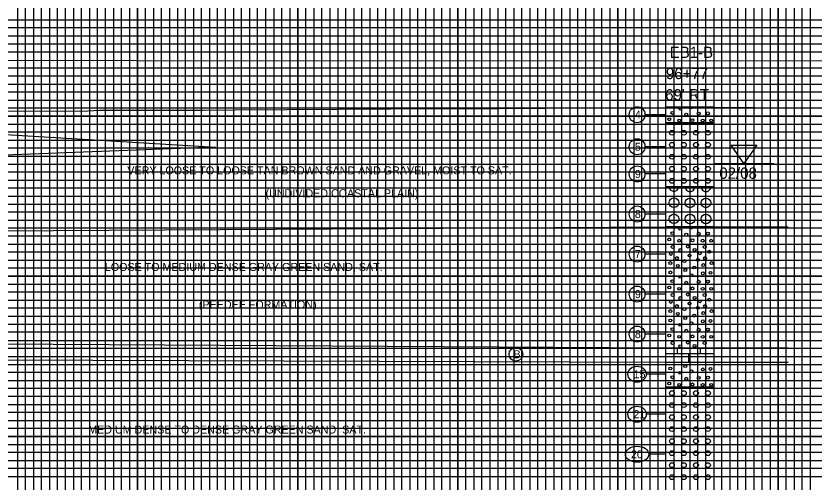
# Model space of a CAD drawing. Extents: x -13 to 886, y -5 to 434.
# Drawn here: x 707.1 to 806.7, y 265.2 to 323.4 of the extents above; entities that cross this region are included whole.
import ezdxf

# ---------------------------------------------------------------- set-up
doc = ezdxf.new("R2010")
doc.units = 0
for name, color, linetype in [('Exist XS Ground Line', 7, 'Continuous'), ('Prop Road Sect_ Boring - Header Labels from Geopak', 7, 'Continuous'), ('Prop Road Sect_ Boring - Material (Outline)', 7, 'Continuous'), ('Prop Road Sect_ Boring - Peripheral (24 Hr GrdWtr Date)', 7, 'Continuous'), ('Prop Road Sect_ Boring - Peripheral (SPT Oval + Leader)', 7, 'Continuous'), ('Prop Road Sect_ Boring - Peripheral (SPT Tx)', 7, 'Continuous'), ('Prop Road Sect_ Material - Contact (General - Minor)', 7, 'Continuous'), ('Prop Road Sect_ Material - Tx (Composite Desc)', 7, 'Continuous'), ('Sheet Cross Section Grid Major CELL', 7, 'Continuous'), ('Sheet Cross Section Grid Middle CELL', 7, 'Continuous'), ('Sheet Cross Section Grid Minor 1 CELL', 7, 'Continuous'), ('Sheet Cross Section Grid Minor 2 CELL', 7, 'Continuous'), ('Sheet DOT Grid CELL', 7, 'Continuous'), ('Water Mark (24 Hr) Cell', 7, 'Continuous')]:
    doc.layers.add(name, color=color, linetype=linetype)

msp = doc.modelspace()

# ---------------------------------------------------------------- linework, layer by layer
at = {"layer": 'Exist XS Ground Line'}
for points in [[(650.115, 311.763), (652.113, 311.781), (666.089, 311.684), (668.65, 311.535), (672.715, 311.547), (682.507, 311.512), (686.055, 311.503), (690.603, 311.476), (715.981, 311.545), (717.469, 311.623), (722.243, 311.635), (730.438, 311.655), (734.382, 311.675), (760.339, 311.838), (767.402, 311.852), (778.837, 311.921), (784.232, 311.947)], [(785.181, 311.951), (799.343, 312.019)]]:
    msp.add_lwpolyline(points, dxfattribs=at)
at = {"layer": 'Prop Road Sect_ Boring - Material (Outline)'}
for p, q in [((788.25, 281.97), (794.237, 281.97)), ((788.25, 280.171), (794.237, 280.171))]:
    msp.add_line(p, q, dxfattribs=at)
for points in [[(788.243, 312.077), (794.243, 312.077), (794.243, 310.077), (788.243, 310.077)], [(788.243, 310.077), (794.243, 310.077), (794.243, 302.077), (788.243, 302.077)], [(788.243, 302.077), (794.243, 302.077), (794.243, 297.077), (788.243, 297.077)], [(788.243, 297.077), (794.243, 297.077), (794.243, 277.077), (788.243, 277.077)], [(788.243, 277.077), (794.243, 277.077), (794.243, 262.077), (788.243, 262.077)]]:
    msp.add_lwpolyline(points, close=True, dxfattribs=at)
for centre, radius in [((789.045, 311.296), 0.18), ((790.026, 311.842), 0.18), ((790.788, 311.107), 0.18), ((792.339, 311.227), 0.18), ((793.485, 311.245), 0.18), ((788.664, 310.51), 0.18), ((789.888, 310.345), 0.18), ((791.55, 310.399), 0.18), ((792.831, 310.345), 0.18), ((793.893, 310.345), 0.18), ((788.99, 308.819), 0.3), ((790.49, 308.819), 0.3), ((791.99, 308.819), 0.3), ((793.49, 308.819), 0.3), ((788.99, 307.322), 0.3), ((790.49, 307.322), 0.3), ((791.99, 307.322), 0.3), ((793.49, 307.322), 0.3), ((788.99, 305.822), 0.3), ((790.49, 305.822), 0.3), ((791.99, 305.822), 0.3), ((793.49, 305.822), 0.3), ((788.99, 304.322), 0.3), ((790.49, 304.322), 0.3), ((791.99, 304.322), 0.3), ((793.49, 304.322), 0.3), ((788.99, 302.822), 0.3), ((790.49, 302.822), 0.3), ((791.99, 302.822), 0.3), ((793.49, 302.822), 0.3), ((789.241, 300.089), 0.6), ((791.251, 300.065), 0.6), ((793.237, 300.065), 0.6), ((789.241, 298.079), 0.6), ((791.251, 298.055), 0.6), ((793.237, 298.055), 0.6), ((789.045, 296.287), 0.18), ((790.026, 296.833), 0.18), ((790.788, 296.098), 0.18), ((792.339, 296.218), 0.18), ((793.485, 296.236), 0.18), ((788.664, 295.501), 0.18), ((789.888, 295.336), 0.18), ((791.55, 295.39), 0.18), ((792.831, 295.336), 0.18), ((793.893, 295.336), 0.18), ((789.082, 294.563), 0.18), ((790.038, 294.173), 0.18), ((790.973, 294.609), 0.18), ((791.82, 294.194), 0.18), ((793.082, 294.563), 0.18), ((793.674, 293.968), 0.18), ((788.856, 293.695), 0.18), ((789.618, 293.179), 0.18), ((791.183, 293.498), 0.18), ((792.231, 292.96), 0.18), ((792.477, 293.776), 0.18), ((793.131, 293.179), 0.18), ((788.802, 292.552), 0.18), ((789.726, 292.198), 0.18), ((790.542, 292.798), 0.18), ((791.784, 291.991), 0.18), ((792.912, 292.306), 0.18), ((793.947, 292.552), 0.18), ((788.802, 291.382), 0.18), ((790.656, 291.682), 0.18), ((791.43, 291.034), 0.18), ((792.858, 291.271), 0.18), ((793.812, 291.328), 0.18), ((789.045, 290.29), 0.18), ((790.026, 290.836), 0.18), ((790.788, 290.101), 0.18), ((792.339, 290.221), 0.18), ((793.485, 290.239), 0.18), ((788.664, 289.504), 0.18), ((789.888, 289.339), 0.18), ((791.55, 289.393), 0.18), ((792.831, 289.339), 0.18), ((793.893, 289.339), 0.18), ((789.082, 288.566), 0.18), ((790.038, 288.176), 0.18), ((790.973, 288.612), 0.18), ((791.82, 288.197), 0.18), ((793.082, 288.566), 0.18), ((793.674, 287.971), 0.18), ((788.856, 287.698), 0.18), ((789.618, 287.182), 0.18), ((791.183, 287.501), 0.18), ((792.231, 286.963), 0.18), ((792.477, 287.779), 0.18), ((793.131, 287.182), 0.18), ((788.802, 286.555), 0.18), ((789.726, 286.201), 0.18), ((790.542, 286.801), 0.18), ((791.784, 285.994), 0.18), ((792.912, 286.309), 0.18), ((793.947, 286.555), 0.18), ((788.802, 285.385), 0.18), ((790.656, 285.685), 0.18), ((791.43, 285.037), 0.18), ((792.858, 285.274), 0.18), ((793.812, 285.331), 0.18), ((789.045, 284.293), 0.18), ((790.026, 284.839), 0.18), ((790.788, 284.104), 0.18), ((792.339, 284.224), 0.18), ((793.485, 284.242), 0.18), ((788.664, 283.507), 0.18), ((789.888, 283.342), 0.18), ((791.55, 283.396), 0.18), ((792.831, 283.342), 0.18), ((793.893, 283.342), 0.18), ((789.082, 282.569), 0.18), ((790.038, 282.179), 0.18), ((790.973, 282.615), 0.18), ((791.82, 282.2), 0.18), ((793.082, 282.569), 0.18), ((788.802, 279.388), 0.18), ((790.656, 279.688), 0.18), ((791.43, 279.04), 0.18), ((792.858, 279.277), 0.18), ((793.812, 279.334), 0.18), ((789.045, 278.296), 0.18), ((790.026, 278.842), 0.18), ((790.788, 278.107), 0.18), ((792.339, 278.227), 0.18), ((793.485, 278.245), 0.18), ((788.664, 277.51), 0.18), ((789.888, 277.345), 0.18), ((791.55, 277.399), 0.18), ((792.831, 277.345), 0.18), ((793.893, 277.345), 0.18), ((788.99, 276.316), 0.3), ((790.49, 276.316), 0.3), ((791.99, 276.316), 0.3), ((793.49, 276.316), 0.3), ((788.99, 274.816), 0.3), ((790.49, 274.816), 0.3), ((791.99, 274.816), 0.3), ((793.49, 274.816), 0.3), ((788.99, 273.319), 0.3), ((790.49, 273.319), 0.3), ((791.99, 273.319), 0.3), ((793.49, 273.319), 0.3), ((788.99, 271.819), 0.3), ((790.49, 271.819), 0.3), ((791.99, 271.819), 0.3), ((793.49, 271.819), 0.3), ((788.99, 270.319), 0.3), ((790.49, 270.319), 0.3), ((791.99, 270.319), 0.3), ((793.49, 270.319), 0.3), ((788.99, 268.819), 0.3), ((790.49, 268.819), 0.3), ((791.99, 268.819), 0.3), ((793.49, 268.819), 0.3), ((788.99, 267.322), 0.3), ((790.49, 267.322), 0.3), ((791.99, 267.322), 0.3), ((793.49, 267.322), 0.3), ((788.99, 265.822), 0.3), ((790.49, 265.822), 0.3), ((791.99, 265.822), 0.3), ((793.49, 265.822), 0.3)]:
    msp.add_circle(centre, radius, dxfattribs=at)
for centre, radius, start, end in [((791.43, 312.04), 0.18, 168.2251, 11.7749), ((788.99, 310.319), 0.3, 233.87938, 306.12062), ((790.49, 310.319), 0.3, 233.87938, 306.12062), ((791.99, 310.319), 0.3, 233.87938, 306.12062), ((793.49, 310.319), 0.3, 233.87938, 306.12062), ((789.241, 302.105), 0.6, 182.75672, 357.24328), ((791.251, 302.075), 0.6, 179.89087, 0.10913), ((793.237, 302.075), 0.6, 179.89087, 0.10913), ((791.43, 297.031), 0.18, 165.28168, 14.71832)]:
    msp.add_arc(centre, radius, start, end, dxfattribs=at)
at = {"layer": 'Prop Road Sect_ Boring - Peripheral (SPT Oval + Leader)'}
for p, q in [((788.243, 311.077), (785.626, 311.077)), ((788.243, 307.077), (785.626, 307.077)), ((788.243, 303.677), (785.626, 303.677)), ((788.243, 298.677), (785.626, 298.677)), ((788.243, 293.677), (785.626, 293.677)), ((788.243, 288.677), (785.626, 288.677)), ((788.243, 283.677), (785.626, 283.677)), ((788.25, 281.249), (793.995, 281.249)), ((789.682, 281.249), (789.682, 281.967)), ((791.12, 280.171), (791.12, 281.249)), ((792.557, 281.249), (792.557, 281.967)), ((793.998, 281.249), (794.237, 281.249)), ((788.243, 278.677), (785.792, 278.677)), ((788.243, 273.677), (785.792, 273.677)), ((788.243, 268.677), (786.115, 268.677))]:
    msp.add_line(p, q, dxfattribs=at)
for centre, major_axis, ratio in [((784.643, 311.077), (0, 1), 0.983465), ((784.643, 307.077), (0, 1), 0.983465), ((784.643, 303.677), (0, 1), 0.983465), ((784.643, 298.677), (0, 1), 0.983465), ((784.643, 293.677), (0, 1), 0.983465), ((784.643, 288.677), (0, 1), 0.983465), ((784.643, 283.677), (0, 1), 0.983465), ((784.643, 278.677), (1.149, 0), 0.870459), ((784.643, 273.677), (1.149, 0), 0.870459), ((784.643, 268.677), (1.472, 0), 0.679508)]:
    msp.add_ellipse(centre, major_axis=major_axis, ratio=ratio, dxfattribs=at)
at = {"layer": 'Prop Road Sect_ Material - Contact (General - Minor)'}
for p, q in [((691.243, 296.49), (788.243, 297.077)), ((794.243, 297.077), (803.525, 297.077)), ((691.301, 282.545), (788.25, 281.97)), ((794.237, 281.97), (803.519, 281.97)), ((691.301, 280.521), (788.25, 280.171)), ((794.237, 280.171), (803.519, 280.171))]:
    msp.add_line(p, q, dxfattribs=at)
msp.add_lwpolyline([(691.243, 309.49), (731.963, 307.005), (691.243, 305.49)], dxfattribs=at)
at = {"layer": 'Prop Road Sect_ Material - Tx (Composite Desc)'}
msp.add_circle((769.509, 281.166), 0.86, dxfattribs=at)
at = {"layer": 'Sheet Cross Section Grid Major CELL'}
for p, q in [((712.243, 200.903), (712.243, 410.903)), ((722.243, 410.903), (722.243, 200.903)), ((732.243, 200.903), (732.243, 410.903)), ((742.243, 410.903), (742.243, 200.903)), ((752.243, 200.903), (752.243, 410.903)), ((762.243, 410.903), (762.243, 200.903)), ((772.243, 200.903), (772.243, 410.903)), ((782.243, 410.903), (782.243, 200.903)), ((792.243, 200.903), (792.243, 410.903)), ((802.243, 410.903), (802.243, 200.903))]:
    msp.add_line(p, q, dxfattribs=at)
for points in [[(562.243, 320.903), (882.243, 320.903), (882.243, 310.903), (562.243, 310.903)], [(562.243, 300.903), (882.243, 300.903), (882.243, 290.903), (562.243, 290.903)], [(562.243, 280.903), (882.243, 280.903), (882.243, 270.903), (562.243, 270.903)]]:
    msp.add_lwpolyline(points, dxfattribs=at)
at = {"layer": 'Sheet Cross Section Grid Middle CELL'}
for points in [[(707.243, 410.903), (707.243, 200.903), (717.243, 200.903), (717.243, 410.903)], [(727.243, 410.903), (727.243, 200.903), (737.243, 200.903), (737.243, 410.903)], [(747.243, 410.903), (747.243, 200.903), (757.243, 200.903), (757.243, 410.903)], [(767.243, 410.903), (767.243, 200.903), (777.243, 200.903), (777.243, 410.903)], [(787.243, 410.903), (787.243, 200.903), (797.243, 200.903), (797.243, 410.903)], [(562.243, 305.903), (882.243, 305.903), (882.243, 315.903), (562.243, 315.903)], [(562.243, 285.903), (882.243, 285.903), (882.243, 295.903), (562.243, 295.903)], [(562.243, 265.903), (882.243, 265.903), (882.243, 275.903), (562.243, 275.903)]]:
    msp.add_lwpolyline(points, dxfattribs=at)
at = {"layer": 'Sheet Cross Section Grid Minor 1 CELL'}
for points in [[(562.243, 322.903), (882.243, 322.903), (882.243, 321.903), (562.243, 321.903)], [(562.243, 319.903), (882.243, 319.903), (882.243, 318.903), (562.243, 318.903)], [(562.243, 317.893), (882.313, 317.813), (882.243, 316.903), (562.243, 316.903)], [(562.243, 314.903), (882.243, 314.903), (882.243, 313.903), (562.243, 313.903)], [(562.243, 312.903), (882.243, 312.903), (882.243, 311.903), (562.243, 311.903)], [(562.243, 309.903), (882.243, 309.903), (882.243, 308.903), (562.243, 308.903)], [(562.243, 307.903), (882.243, 307.903), (882.243, 306.903), (562.243, 306.903)], [(562.243, 304.903), (882.243, 304.903), (882.243, 303.903), (562.243, 303.903)], [(562.243, 302.903), (882.243, 302.903), (882.243, 301.903), (562.243, 301.903)], [(562.243, 299.903), (882.243, 299.903), (882.243, 298.903), (562.243, 298.903)], [(562.243, 297.903), (882.243, 297.903), (882.243, 296.903), (562.243, 296.903)], [(562.243, 294.903), (882.243, 294.903), (882.243, 293.903), (562.243, 293.903)], [(562.243, 292.903), (882.243, 292.903), (882.243, 291.903), (562.243, 291.903)], [(562.243, 289.903), (882.243, 289.903), (882.243, 288.903), (562.243, 288.903)], [(562.243, 287.903), (882.243, 287.903), (882.243, 286.903), (562.243, 286.903)], [(562.243, 284.903), (882.243, 284.903), (882.243, 283.903), (562.243, 283.903)], [(562.243, 282.903), (882.243, 282.903), (882.243, 281.903), (562.243, 281.903)], [(562.243, 279.903), (882.243, 279.903), (882.233, 278.883), (562.243, 278.903)], [(562.243, 277.903), (882.243, 277.903), (882.243, 276.903), (562.243, 276.903)], [(562.243, 274.903), (882.243, 274.903), (882.243, 273.903), (562.243, 273.903)], [(562.243, 272.903), (882.243, 272.903), (882.243, 271.903), (562.243, 271.903)], [(562.243, 269.903), (882.243, 269.903), (882.243, 268.903), (562.243, 268.903)], [(562.243, 267.903), (882.243, 267.903), (882.243, 266.903), (562.243, 266.903)]]:
    msp.add_lwpolyline(points, dxfattribs=at)
at = {"layer": 'Sheet Cross Section Grid Minor 2 CELL'}
for points in [[(707.243, 200.903), (708.243, 200.903), (708.243, 410.903), (709.243, 410.903), (709.243, 200.903)], [(709.243, 200.903), (710.243, 200.903), (710.243, 410.903), (711.243, 410.903), (711.243, 200.903)], [(712.243, 200.903), (713.243, 200.903), (713.243, 410.903), (714.243, 410.903), (714.243, 200.903)], [(714.243, 200.903), (715.243, 200.903), (715.243, 410.903), (716.243, 410.903), (716.243, 200.903)], [(717.243, 200.903), (718.243, 200.903), (718.243, 410.903), (719.243, 410.903), (719.243, 200.903)], [(719.243, 200.903), (720.243, 200.903), (720.243, 410.903), (721.243, 410.903), (721.243, 200.903)], [(722.243, 200.903), (723.243, 200.903), (723.243, 410.903), (724.243, 410.903), (724.243, 200.903)], [(724.243, 200.903), (725.243, 200.903), (725.243, 410.903), (726.243, 410.903), (726.243, 200.903)], [(727.243, 200.903), (728.243, 200.903), (728.243, 410.903), (729.243, 410.903), (729.243, 200.903)], [(729.243, 200.903), (730.243, 200.903), (730.243, 410.903), (731.243, 410.903), (731.243, 200.903)], [(732.243, 200.903), (733.243, 200.903), (733.243, 410.903), (734.243, 410.903), (734.243, 200.903)], [(734.243, 200.903), (735.243, 200.903), (735.243, 410.903), (736.243, 410.903), (736.243, 200.903)], [(737.243, 200.903), (738.243, 200.903), (738.243, 410.903), (739.243, 410.903), (739.243, 200.903)], [(739.243, 200.903), (740.243, 200.903), (740.243, 410.903), (741.243, 410.903), (741.243, 200.903)], [(742.243, 200.903), (743.243, 200.903), (743.243, 410.903), (744.243, 410.903), (744.243, 200.903)], [(744.243, 200.903), (745.243, 200.903), (745.243, 410.903), (746.243, 410.903), (746.243, 200.903)], [(747.243, 200.903), (748.243, 200.903), (748.243, 410.903), (749.243, 410.903), (749.243, 200.903)], [(749.243, 200.903), (750.243, 200.903), (750.243, 410.903), (751.243, 410.903), (751.243, 200.903)], [(752.243, 200.903), (753.243, 200.903), (753.243, 410.903), (754.243, 410.903), (754.243, 200.903)], [(754.243, 200.903), (755.243, 200.903), (755.243, 410.903), (756.243, 410.903), (756.243, 200.903)], [(757.243, 200.903), (758.243, 200.903), (758.243, 410.903), (759.243, 410.903), (759.243, 200.903)], [(759.243, 200.903), (760.243, 200.903), (760.243, 410.903), (761.243, 410.903), (761.243, 200.903)], [(762.243, 200.903), (763.243, 200.903), (763.243, 410.903), (764.243, 410.903), (764.243, 200.903)], [(764.243, 200.903), (765.243, 200.903), (765.243, 410.903), (766.243, 410.903), (766.243, 200.903)], [(767.243, 200.903), (768.243, 200.903), (768.243, 410.903), (769.243, 410.903), (769.243, 200.903)], [(769.243, 200.903), (770.243, 200.903), (770.243, 410.903), (771.243, 410.903), (771.243, 200.903)], [(772.243, 200.903), (773.243, 200.903), (773.243, 410.903), (774.243, 410.903), (774.243, 200.903)], [(774.243, 200.903), (775.243, 200.903), (775.243, 410.903), (776.243, 410.903), (776.243, 200.903)], [(777.243, 200.903), (778.243, 200.903), (778.243, 410.903), (779.243, 410.903), (779.243, 200.903)], [(779.243, 200.903), (780.243, 200.903), (780.243, 410.903), (781.243, 410.903), (781.243, 200.903)], [(782.243, 200.903), (783.243, 200.903), (783.243, 410.903), (784.243, 410.903), (784.243, 200.903)], [(784.243, 200.903), (785.243, 200.903), (785.243, 410.903), (786.243, 410.903), (786.243, 200.903)], [(787.243, 200.903), (788.243, 200.903), (788.243, 410.903), (789.243, 410.903), (789.243, 200.903)], [(789.243, 200.903), (790.243, 200.903), (790.243, 410.903), (791.243, 410.903), (791.243, 200.903)], [(792.243, 200.903), (793.243, 200.903), (793.243, 410.903), (794.243, 410.903), (794.243, 200.903)], [(794.243, 200.903), (795.243, 200.903), (795.243, 410.903), (796.243, 410.903), (796.243, 200.903)], [(797.243, 200.903), (798.243, 200.903), (798.243, 410.903), (799.243, 410.903), (799.243, 200.903)], [(799.243, 200.903), (800.243, 200.903), (800.243, 410.903), (801.243, 410.903), (801.243, 200.903)], [(802.243, 200.903), (803.243, 200.903), (803.243, 410.903), (804.243, 410.903), (804.243, 200.903)], [(804.243, 200.903), (805.243, 200.903), (805.243, 410.903), (806.243, 410.903), (806.243, 200.903)]]:
    msp.add_lwpolyline(points, dxfattribs=at)
at = {"layer": 'Sheet DOT Grid CELL'}
for p, q in [((712.243, 200.903), (712.243, 410.903)), ((722.243, 200.903), (722.243, 410.903)), ((732.243, 200.903), (732.243, 410.903)), ((742.243, 200.903), (742.243, 410.903)), ((752.243, 200.903), (752.243, 410.903)), ((762.243, 200.903), (762.243, 410.903)), ((772.243, 200.903), (772.243, 410.903)), ((782.243, 200.903), (782.243, 410.903)), ((792.243, 200.903), (792.243, 410.903)), ((802.243, 200.903), (802.243, 410.903)), ((562.243, 320.903), (882.243, 320.903)), ((562.243, 310.903), (882.243, 310.903)), ((562.243, 300.903), (882.243, 300.903)), ((562.243, 290.903), (882.243, 290.903)), ((562.243, 280.903), (882.243, 280.903)), ((562.243, 270.903), (882.243, 270.903))]:
    msp.add_line(p, q, dxfattribs=at)
at = {"layer": 'Water Mark (24 Hr) Cell'}
for p, q in [((794.243, 304.977), (797.993, 304.977)), ((797.993, 304.977), (801.743, 304.977))]:
    msp.add_line(p, q, dxfattribs=at)
msp.add_lwpolyline([(796.38, 307.283), (799.605, 307.283), (797.993, 304.977)], close=True, dxfattribs=at)

# ---------------------------------------------------------------- texts
at = {"layer": 'Prop Road Sect_ Boring - Header Labels from Geopak'}
for s, p in [('EB1-B', (788.718, 318.166)), ('96+77', (788.244, 315.516)), ("69' RT", (788.156, 312.866))]:
    msp.add_text(s, height=1.4, dxfattribs=at).set_placement(p)
at = {"layer": 'Prop Road Sect_ Boring - Peripheral (24 Hr GrdWtr Date)'}
msp.add_text('02/08', height=1.4, dxfattribs=at).set_placement((794.917, 303.077))
at = {"layer": 'Prop Road Sect_ Boring - Peripheral (SPT Tx)'}
for s, p in [('4', (784.359, 310.577)), ('5', (784.359, 306.577)), ('9', (784.359, 303.177)), ('8', (784.359, 298.177)), ('7', (784.359, 293.177)), ('9', (784.359, 288.177)), ('8', (784.359, 283.177)), ('15', (784.194, 278.177)), ('21', (784.194, 273.177)), ('20', (783.871, 268.177))]:
    msp.add_text(s, height=1, dxfattribs=at).set_placement(p)
at = {"layer": 'Prop Road Sect_ Material - Tx (Composite Desc)'}
for s, p in [('VERY LOOSE TO LOOSE TAN BROWN SAND AND GRAVEL, MOIST TO SAT.', (720.965, 303.624)), ('(UNDIVIDED COASTAL PLAIN)', (738.232, 300.767)), ('LOOSE TO MEDIUM DENSE GRAY GREEN SAND, SAT.', (718.154, 291.565)), ('(PEEDEE FORMATION)', (729.894, 286.869)), ('B', (769.202, 280.666)), ('MEDIUM DENSE TO DENSE GRAY GREEN SAND, SAT.', (716.075, 271.264))]:
    msp.add_text(s, height=1, dxfattribs=at).set_placement(p)

doc.saveas('drawing.dxf')
